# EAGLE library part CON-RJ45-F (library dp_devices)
HR911105A Female Ethernet RJ-45 with internal transformer and 2 LEDs
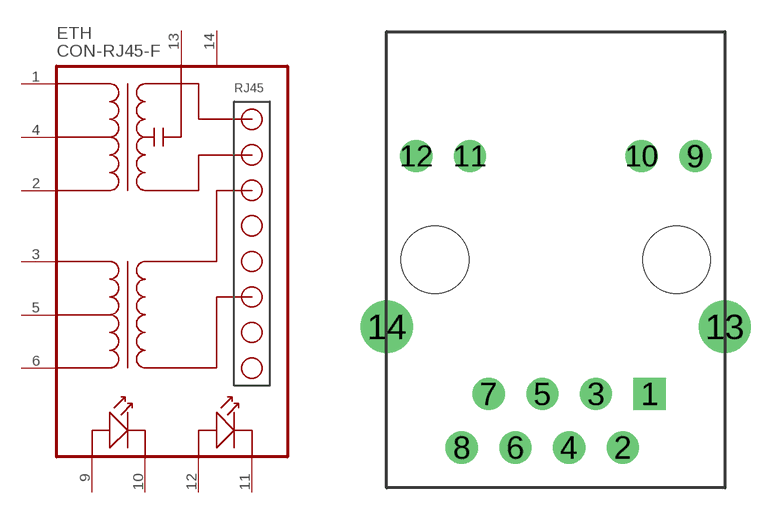
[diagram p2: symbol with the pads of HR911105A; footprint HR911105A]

Designator prefix ETH

## CON-RJ45-F  [HR911105A]
1  1
2  2
3  3
4  4
5  5
6  6
9  9
10  10
11  11
12  12
13  13
14  14

## Footprint HR911105A (pad centres in mm)
drill 0.813 pad 1.524 square: 1 4.445,-6.35
drill 0.813 pad 1.524 round: 2 3.175,-8.89; 3 1.905,-6.35; 4 0.635,-8.89; 5 -0.635,-6.35; 6 -1.905,-8.89; 7 -3.175,-6.35; 8 -4.445,-8.89; 9 6.604,4.902; 10 4.064,4.902; 11 -4.064,4.902; 12 -6.604,4.902
drill 1.651 pad 2.159 round: 13 8.001,-3.175; 14 -8.001,-3.175
hole 3.2 at 5.715,0
hole 3.2 at -5.715,0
